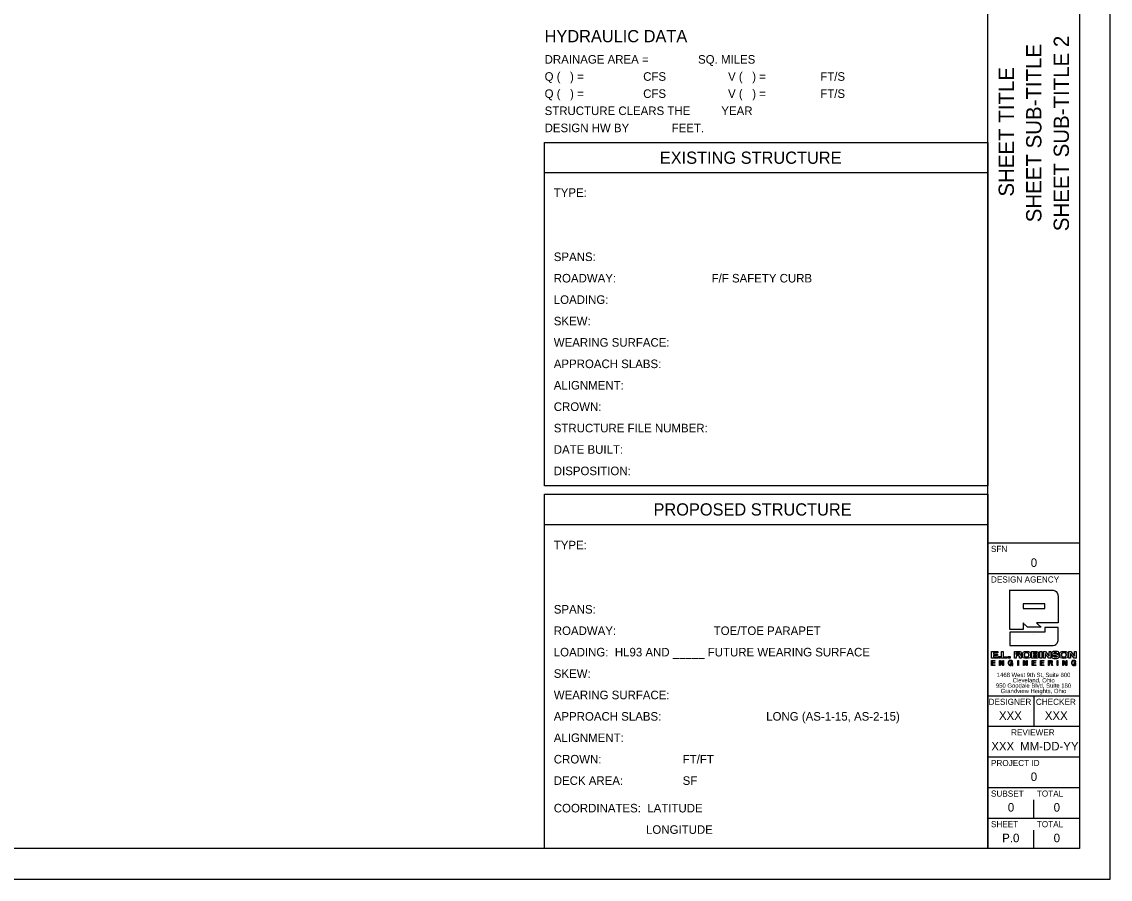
# Model space of a CAD drawing. Extents: x -1.6 to 34, y 0 to 22.
# Drawn here: x 16.2 to 34, y 0 to 14.02 of the extents above; entities that cross this region are included whole.
import ezdxf

# ---------------------------------------------------------------- set-up
doc = ezdxf.new("R2010")
doc.units = 0
for name, color, linetype in [('Default', 7, 'Continuous'), ('SH_Border', 7, 'Continuous'), ('SH_Cut_Line', 7, 'Continuous'), ('SH_Data', 7, 'Continuous')]:
    doc.layers.add(name, color=color, linetype=linetype)

msp = doc.modelspace()

# ---------------------------------------------------------------- linework, layer by layer
at = {"layer": 'SH_Border'}
for p, q in [((32, 0.5), (32, 21.5)), ((32, 5.5), (33.5, 5.5)), ((32, 5), (33.5, 5)), ((32, 3), (33.5, 3)), ((32.75, 3), (32.75, 2.5)), ((32, 2.5), (33.5, 2.5)), ((32, 2), (33.5, 2)), ((32, 1.5), (33.5, 1.5)), ((32, 1), (33.5, 1))]:
    msp.add_line(p, q, dxfattribs=at)
msp.add_lwpolyline([(1.5, 21.5), (33.5, 21.5), (33.5, 0.5), (1.5, 0.5)], close=True, dxfattribs=at)
at = {"layer": 'SH_Cut_Line'}
msp.add_lwpolyline([(0, 0), (34, 0), (34, 22), (0, 22)], close=True, dxfattribs=at)
at = {"layer": 'SH_Data'}
for p, q in [((32, 11.545), (24.75, 11.545)), ((32, 5.795), (24.75, 5.795)), ((32.929, 4.503), (32.574, 4.503)), ((32.574, 4.503), (32.574, 4.425)), ((32.929, 4.425), (32.929, 4.503)), ((32.574, 4.425), (32.929, 4.425)), ((32.75, 4), (32.75, 4)), ((32.463, 3.701), (32.463, 3.673)), ((32.743, 3.702), (32.743, 3.678)), ((32.743, 3.659), (32.743, 3.633)), ((33.001, 3.566), (33.001, 3.539)), ((33.001, 3.539), (33.023, 3.539)), ((32.75, 1), (32.75, 1.3)), ((32.75, 0.5), (32.75, 0.8)), ((32.375, 0.675), (32.375, 0.675))]:
    msp.add_line(p, q, dxfattribs=at)
for points in [[(24.75, 12.045), (32, 12.045), (32, 6.431), (24.75, 6.431)], [(24.75, 6.295), (32, 6.295), (32, 0.5), (24.75, 0.5)]]:
    msp.add_lwpolyline(points, close=True, dxfattribs=at)
for points in [[(32.059, 3.575), (32.114, 3.575), (32.114, 3.566), (32.07, 3.566), (32.07, 3.541), (32.111, 3.541), (32.111, 3.532), (32.07, 3.532), (32.07, 3.505), (32.114, 3.505), (32.114, 3.496), (32.059, 3.496), (32.059, 3.575)], [(32.06, 3.721), (32.161, 3.721), (32.161, 3.701), (32.089, 3.701), (32.089, 3.678), (32.158, 3.678), (32.158, 3.658), (32.089, 3.658), (32.089, 3.633), (32.162, 3.633), (32.162, 3.613), (32.06, 3.613), (32.06, 3.721)], [(32.175, 3.639), (32.205, 3.639), (32.205, 3.613), (32.175, 3.613), (32.175, 3.639)], [(32.191, 3.575), (32.203, 3.575), (32.244, 3.511), (32.244, 3.511), (32.244, 3.575), (32.254, 3.575), (32.254, 3.496), (32.243, 3.496), (32.202, 3.559), (32.201, 3.559), (32.201, 3.496), (32.191, 3.496), (32.191, 3.575)], [(32.22, 3.721), (32.249, 3.721), (32.249, 3.634), (32.316, 3.634), (32.316, 3.613), (32.22, 3.613), (32.22, 3.721)], [(32.331, 3.639), (32.361, 3.639), (32.361, 3.613), (32.331, 3.613), (32.331, 3.639)], [(32.487, 3.575), (32.498, 3.575), (32.498, 3.496), (32.487, 3.496), (32.487, 3.575)], [(32.581, 3.575), (32.592, 3.575), (32.633, 3.511), (32.633, 3.511), (32.633, 3.575), (32.643, 3.575), (32.643, 3.496), (32.632, 3.496), (32.591, 3.559), (32.591, 3.559), (32.591, 3.496), (32.581, 3.496), (32.581, 3.575)], [(32.726, 3.575), (32.781, 3.575), (32.781, 3.566), (32.737, 3.566), (32.737, 3.541), (32.778, 3.541), (32.778, 3.532), (32.737, 3.532), (32.737, 3.505), (32.781, 3.505), (32.781, 3.496), (32.726, 3.496), (32.726, 3.575)], [(32.851, 3.721), (32.881, 3.721), (32.881, 3.613), (32.851, 3.613), (32.851, 3.721)], [(32.859, 3.575), (32.913, 3.575), (32.913, 3.566), (32.869, 3.566), (32.869, 3.541), (32.91, 3.541), (32.91, 3.532), (32.869, 3.532), (32.869, 3.505), (32.913, 3.505), (32.913, 3.496), (32.859, 3.496), (32.859, 3.575)], [(32.999, 3.721), (33.027, 3.721), (33.027, 3.613), (32.995, 3.613), (32.936, 3.689), (32.936, 3.689), (32.936, 3.613), (32.907, 3.613), (32.907, 3.721), (32.941, 3.721), (32.999, 3.646), (32.999, 3.646), (32.999, 3.721)], [(33.133, 3.575), (33.143, 3.575), (33.143, 3.496), (33.133, 3.496), (33.133, 3.575)], [(33.226, 3.575), (33.237, 3.575), (33.279, 3.511), (33.279, 3.511), (33.279, 3.575), (33.289, 3.575), (33.289, 3.496), (33.277, 3.496), (33.236, 3.559), (33.236, 3.559), (33.236, 3.496), (33.226, 3.496), (33.226, 3.575)], [(33.413, 3.721), (33.442, 3.721), (33.442, 3.613), (33.41, 3.613), (33.35, 3.689), (33.35, 3.689), (33.35, 3.613), (33.321, 3.613), (33.321, 3.721), (33.356, 3.721), (33.413, 3.646), (33.413, 3.646), (33.413, 3.721)]]:
    msp.add_lwpolyline(points, dxfattribs=at)
for points, degree in [([(32.356, 4.083), (32.356, 4.086), (32.356, 4.724), (32.356, 4.727)], 2), ([(32.356, 4.727), (32.36, 4.727), (33.03, 4.727), (33.034, 4.727), (33.096, 4.727), (33.147, 4.677), (33.147, 4.614)], 3), ([(33.147, 4.614), (33.147, 4.612), (33.147, 4.194), (33.147, 4.192)], 2), ([(32.929, 4.115), (32.929, 4.115), (33.147, 4.115), (33.147, 4.115), (33.147, 4.115), (33.147, 3.933), (33.147, 3.933), (33.147, 3.87), (33.096, 3.82), (33.034, 3.82), (33.034, 3.82), (32.356, 3.82), (32.356, 3.82), (32.356, 3.82), (32.356, 4.037), (32.356, 4.037), (32.356, 4.037), (32.929, 4.037), (32.929, 4.037), (32.929, 4.037), (32.929, 4.115), (32.929, 4.115)], 3), ([(32.645, 4.121), (32.645, 4.121), (32.574, 4.191), (32.574, 4.192)], 2), ([(32.574, 4.192), (32.574, 4.191), (32.574, 4.083), (32.574, 4.083)], 2), ([(32.866, 4.121), (32.865, 4.121), (32.646, 4.121), (32.645, 4.121)], 2), ([(33.147, 4.192), (33.145, 4.192), (32.795, 4.192), (32.793, 4.192)], 2), ([(32.793, 4.192), (32.793, 4.191), (32.866, 4.121), (32.866, 4.121)], 2), ([(32.574, 4.083), (32.573, 4.083), (32.357, 4.083), (32.356, 4.083)], 2), ([(32.396, 3.506), (32.39, 3.498), (32.38, 3.494), (32.37, 3.494), (32.347, 3.494), (32.333, 3.514), (32.333, 3.534), (32.333, 3.557), (32.346, 3.577), (32.37, 3.577), (32.388, 3.577), (32.401, 3.569), (32.404, 3.551), (32.404, 3.551), (32.394, 3.551), (32.394, 3.551), (32.392, 3.562), (32.382, 3.568), (32.37, 3.568), (32.351, 3.568), (32.344, 3.551), (32.344, 3.534), (32.344, 3.518), (32.353, 3.503), (32.37, 3.503), (32.387, 3.503), (32.396, 3.515), (32.396, 3.529), (32.396, 3.529), (32.371, 3.529), (32.371, 3.529), (32.371, 3.529), (32.371, 3.538), (32.371, 3.538), (32.371, 3.538), (32.405, 3.538), (32.405, 3.538), (32.405, 3.538), (32.405, 3.496), (32.405, 3.496), (32.405, 3.496), (32.398, 3.496), (32.398, 3.496), (32.398, 3.496), (32.396, 3.506), (32.396, 3.506)], 3), ([(32.433, 3.613), (32.433, 3.613), (32.433, 3.721), (32.433, 3.721)], 2), ([(32.433, 3.721), (32.433, 3.721), (32.512, 3.721), (32.512, 3.721), (32.542, 3.721), (32.545, 3.703), (32.546, 3.692)], 3), ([(32.463, 3.613), (32.462, 3.613), (32.433, 3.613), (32.433, 3.613)], 2), ([(32.499, 3.653), (32.499, 3.653), (32.463, 3.653), (32.463, 3.653)], 2), ([(32.463, 3.673), (32.463, 3.673), (32.502, 3.673), (32.502, 3.673), (32.508, 3.673), (32.516, 3.677), (32.516, 3.687), (32.516, 3.698), (32.507, 3.701), (32.5, 3.701), (32.5, 3.701), (32.463, 3.701), (32.463, 3.701), (32.463, 3.701), (32.463, 3.673), (32.463, 3.673)], 3), ([(32.463, 3.673), (32.476, 3.673), (32.489, 3.673), (32.508, 3.673), (32.516, 3.677), (32.516, 3.698), (32.507, 3.701), (32.488, 3.701), (32.475, 3.701), (32.463, 3.701)], 3), ([(32.463, 3.653), (32.463, 3.652), (32.463, 3.613), (32.463, 3.613)], 2), ([(32.518, 3.613), (32.516, 3.618), (32.516, 3.622), (32.516, 3.634), (32.515, 3.649), (32.508, 3.65), (32.499, 3.653)], 3), ([(32.55, 3.613), (32.55, 3.613), (32.518, 3.613), (32.518, 3.613)], 2), ([(32.546, 3.692), (32.544, 3.679), (32.542, 3.67), (32.53, 3.666)], 2), ([(32.53, 3.666), (32.53, 3.666), (32.53, 3.665), (32.53, 3.665)], 2), ([(32.53, 3.665), (32.543, 3.663), (32.544, 3.647), (32.544, 3.636)], 2), ([(32.544, 3.636), (32.544, 3.631), (32.548, 3.619), (32.55, 3.613)], 2), ([(32.631, 3.61), (32.573, 3.61), (32.567, 3.645), (32.565, 3.667), (32.564, 3.69), (32.573, 3.724), (32.631, 3.724)], 3), ([(32.631, 3.63), (32.658, 3.63), (32.667, 3.65), (32.667, 3.667), (32.667, 3.684), (32.658, 3.704), (32.631, 3.704), (32.604, 3.704), (32.595, 3.684), (32.595, 3.667), (32.595, 3.65), (32.604, 3.63), (32.631, 3.63)], 3), ([(32.631, 3.704), (32.604, 3.704), (32.595, 3.684), (32.595, 3.667), (32.595, 3.65), (32.604, 3.63), (32.631, 3.63)], 3), ([(32.631, 3.724), (32.69, 3.724), (32.695, 3.689), (32.697, 3.667), (32.699, 3.644), (32.69, 3.61), (32.631, 3.61)], 3), ([(32.631, 3.63), (32.658, 3.63), (32.667, 3.65), (32.667, 3.667), (32.667, 3.684), (32.658, 3.704), (32.631, 3.704)], 3), ([(32.714, 3.613), (32.714, 3.613), (32.714, 3.721), (32.714, 3.721)], 2), ([(32.714, 3.721), (32.714, 3.721), (32.795, 3.721), (32.795, 3.721)], 2), ([(32.829, 3.645), (32.827, 3.632), (32.824, 3.613), (32.791, 3.613), (32.791, 3.613), (32.714, 3.613), (32.714, 3.613)], 3), ([(32.743, 3.678), (32.743, 3.678), (32.784, 3.678), (32.784, 3.678), (32.791, 3.678), (32.796, 3.682), (32.796, 3.69), (32.796, 3.697), (32.793, 3.702), (32.78, 3.702), (32.78, 3.702), (32.743, 3.702), (32.743, 3.702), (32.743, 3.702), (32.743, 3.678), (32.743, 3.678)], 3), ([(32.743, 3.678), (32.757, 3.678), (32.771, 3.678), (32.791, 3.681), (32.791, 3.683), (32.792, 3.697), (32.793, 3.702), (32.768, 3.702), (32.756, 3.702), (32.743, 3.702)], 3), ([(32.743, 3.633), (32.743, 3.633), (32.787, 3.633), (32.787, 3.633), (32.796, 3.633), (32.8, 3.639), (32.8, 3.646), (32.8, 3.655), (32.794, 3.659), (32.784, 3.659), (32.784, 3.659), (32.743, 3.659), (32.743, 3.659), (32.743, 3.659), (32.743, 3.633), (32.743, 3.633)], 3), ([(32.743, 3.633), (32.758, 3.633), (32.772, 3.633), (32.796, 3.633), (32.8, 3.639), (32.8, 3.655), (32.794, 3.659), (32.77, 3.659), (32.757, 3.659), (32.743, 3.659)], 3), ([(32.795, 3.721), (32.81, 3.718), (32.826, 3.714), (32.826, 3.694)], 2), ([(32.826, 3.694), (32.824, 3.686), (32.822, 3.675), (32.812, 3.672)], 2), ([(32.812, 3.672), (32.812, 3.672), (32.812, 3.672), (32.812, 3.672)], 2), ([(32.812, 3.672), (32.824, 3.67), (32.827, 3.656), (32.829, 3.645)], 2), ([(32.991, 3.575), (32.991, 3.575), (33.027, 3.575), (33.028, 3.575), (33.042, 3.575), (33.051, 3.567), (33.051, 3.554)], 3), ([(32.991, 3.496), (32.991, 3.497), (32.991, 3.574), (32.991, 3.575)], 2), ([(33.023, 3.539), (33.033, 3.539), (33.041, 3.541), (33.041, 3.552), (33.041, 3.56), (33.037, 3.566), (33.027, 3.566), (33.027, 3.566), (33.001, 3.566), (33.001, 3.566), (33.001, 3.566), (33.001, 3.539), (33.001, 3.539), (33.001, 3.539), (33.023, 3.539), (33.023, 3.539)], 3), ([(33.023, 3.539), (33.033, 3.539), (33.041, 3.541), (33.041, 3.56), (33.037, 3.566), (33.018, 3.566), (33.01, 3.566), (33.001, 3.566)], 3), ([(33.126, 3.69), (33.124, 3.704), (33.111, 3.706), (33.099, 3.706), (33.087, 3.706), (33.079, 3.7), (33.079, 3.693), (33.079, 3.687), (33.084, 3.684), (33.091, 3.683), (33.091, 3.683), (33.128, 3.677), (33.128, 3.677), (33.148, 3.673), (33.163, 3.666), (33.163, 3.646), (33.163, 3.626), (33.149, 3.61), (33.107, 3.61), (33.08, 3.61), (33.046, 3.613), (33.045, 3.647), (33.045, 3.647), (33.079, 3.647), (33.079, 3.647), (33.079, 3.632), (33.094, 3.629), (33.107, 3.629), (33.121, 3.629), (33.13, 3.634), (33.13, 3.643), (33.13, 3.651), (33.123, 3.654), (33.112, 3.655), (33.112, 3.655), (33.085, 3.66), (33.085, 3.66), (33.066, 3.662), (33.047, 3.668), (33.047, 3.69), (33.047, 3.715), (33.067, 3.724), (33.101, 3.724), (33.124, 3.724), (33.157, 3.721), (33.159, 3.69), (33.159, 3.69), (33.126, 3.69), (33.126, 3.69)], 3), ([(33.242, 3.61), (33.183, 3.61), (33.178, 3.645), (33.176, 3.667), (33.174, 3.69), (33.183, 3.724), (33.242, 3.724)], 3), ([(33.242, 3.63), (33.269, 3.63), (33.278, 3.65), (33.278, 3.667), (33.278, 3.684), (33.269, 3.704), (33.242, 3.704), (33.215, 3.704), (33.205, 3.684), (33.205, 3.667), (33.205, 3.65), (33.215, 3.63), (33.242, 3.63)], 3), ([(33.242, 3.704), (33.215, 3.704), (33.205, 3.684), (33.205, 3.667), (33.205, 3.65), (33.215, 3.63), (33.242, 3.63)], 3), ([(33.242, 3.724), (33.3, 3.724), (33.306, 3.689), (33.308, 3.667), (33.309, 3.644), (33.3, 3.61), (33.242, 3.61)], 3), ([(33.242, 3.63), (33.269, 3.63), (33.278, 3.65), (33.278, 3.667), (33.278, 3.684), (33.269, 3.704), (33.242, 3.704)], 3), ([(33.43, 3.506), (33.424, 3.498), (33.414, 3.494), (33.405, 3.494), (33.382, 3.494), (33.368, 3.514), (33.368, 3.534), (33.368, 3.557), (33.38, 3.577), (33.405, 3.577), (33.422, 3.577), (33.436, 3.569), (33.439, 3.551), (33.439, 3.551), (33.429, 3.551), (33.429, 3.551), (33.426, 3.562), (33.417, 3.568), (33.405, 3.568), (33.386, 3.568), (33.378, 3.551), (33.378, 3.534), (33.378, 3.518), (33.388, 3.503), (33.405, 3.503), (33.421, 3.503), (33.431, 3.515), (33.43, 3.529), (33.43, 3.529), (33.405, 3.529), (33.405, 3.529), (33.405, 3.529), (33.405, 3.538), (33.405, 3.538), (33.405, 3.538), (33.44, 3.538), (33.44, 3.538), (33.44, 3.538), (33.44, 3.496), (33.44, 3.496), (33.44, 3.496), (33.433, 3.496), (33.433, 3.496), (33.433, 3.496), (33.43, 3.506), (33.43, 3.506)], 3), ([(33.001, 3.496), (33.001, 3.496), (32.991, 3.496), (32.991, 3.496)], 2), ([(33.04, 3.516), (33.038, 3.523), (33.037, 3.53), (33.027, 3.53), (33.027, 3.53), (33.001, 3.53), (33.001, 3.53)], 3), ([(33.001, 3.53), (33.001, 3.53), (33.001, 3.496), (33.001, 3.496)], 2), ([(33.051, 3.554), (33.049, 3.545), (33.047, 3.537), (33.038, 3.534)], 2), ([(33.038, 3.534), (33.038, 3.534), (33.038, 3.534), (33.038, 3.534)], 2), ([(33.038, 3.534), (33.044, 3.529), (33.047, 3.525), (33.048, 3.518)], 2), ([(33.043, 3.496), (33.042, 3.5), (33.041, 3.508), (33.04, 3.516)], 2), ([(33.054, 3.496), (33.054, 3.496), (33.043, 3.496), (33.043, 3.496)], 2), ([(33.048, 3.518), (33.049, 3.51), (33.052, 3.502), (33.054, 3.496)], 2)]:
    msp.add_open_spline(points, degree=degree, dxfattribs=at)

# ---------------------------------------------------------------- texts
at = {"layer": 'Default'}
msp.add_text('0', height=0.14, dxfattribs=at).set_placement((32.7, 5.105))
at = {"layer": 'SH_Data'}
for s, height, p in [('HYDRAULIC DATA', 0.2, (24.75, 13.682)), ('DRAINAGE AREA =', 0.14, (24.75, 13.332)), ('SQ. MILES', 0.14, (27.259, 13.332)), ('Q (   ) =', 0.14, (24.75, 13.052)), ('      CFS', 0.14, (26.05, 13.052)), ('V (   ) =', 0.14, (27.75, 13.052)), ('    FT/S', 0.14, (29.05, 13.052)), ('Q (   ) =', 0.14, (24.75, 12.772)), ('      CFS', 0.14, (26.05, 12.772)), ('V (   ) =', 0.14, (27.75, 12.772)), ('    FT/S', 0.14, (29.05, 12.772)), ('STRUCTURE CLEARS THE', 0.14, (24.75, 12.492)), ('YEAR', 0.14, (27.64, 12.492)), ('DESIGN HW BY', 0.14, (24.75, 12.212)), ('FEET.', 0.14, (26.827, 12.212)), ('EXISTING STRUCTURE', 0.2, (26.634, 11.695)), ('TYPE:', 0.14, (24.9, 11.155)), ('SPANS:', 0.14, (24.9, 10.105)), ('ROADWAY:', 0.14, (24.9, 9.755)), ('F/F SAFETY CURB', 0.14, (27.481, 9.755)), ('LOADING:', 0.14, (24.9, 9.405)), ('SKEW:', 0.14, (24.9, 9.055)), ('WEARING SURFACE:', 0.14, (24.9, 8.705)), ('APPROACH SLABS:', 0.14, (24.9, 8.355)), ('ALIGNMENT:', 0.14, (24.9, 8.005)), ('CROWN:', 0.14, (24.9, 7.655)), ('STRUCTURE FILE NUMBER:', 0.14, (24.9, 7.305)), ('DATE BUILT:', 0.14, (24.9, 6.955)), ('DISPOSITION:', 0.14, (24.9, 6.605)), ('PROPOSED STRUCTURE', 0.2, (26.531, 5.945)), ('TYPE:', 0.14, (24.9, 5.392)), ('SFN', 0.1, (32.05, 5.35)), ('DESIGN AGENCY', 0.1, (32.05, 4.85)), ('SPANS:', 0.14, (24.9, 4.342)), ('ROADWAY:', 0.14, (24.9, 3.992)), ('TOE/TOE PARAPET', 0.14, (27.515, 3.992)), ('LOADING:  HL93 AND _____ FUTURE WEARING SURFACE', 0.14, (24.9, 3.642)), ('SKEW:', 0.14, (24.9, 3.292)), ('1468 West 9th St, Suite 800', 0.07, (32.145, 3.305)), ('Cleveland, Ohio', 0.07, (32.404, 3.217)), ('WEARING SURFACE:', 0.14, (24.9, 2.942)), ('950 Goodale Blvd, Suite 180', 0.07, (32.13, 3.13)), ('Grandview Heights, Ohio', 0.07, (32.208, 3.042)), ('DESIGNER', 0.1, (32.011, 2.85)), ('CHECKER', 0.1, (32.784, 2.85)), ('APPROACH SLABS:', 0.14, (24.9, 2.592)), ('LONG (AS-1-15, AS-2-15)', 0.14, (28.374, 2.592)), ('XXX', 0.14, (32.18, 2.605)), ('XXX', 0.14, (32.93, 2.605)), ('ALIGNMENT:', 0.14, (24.9, 2.242)), ('REVIEWER', 0.1, (32.378, 2.35)), ('XXX', 0.14, (32.055, 2.105)), ('MM-DD-YY', 0.14, (32.526, 2.105)), ('CROWN:', 0.14, (24.9, 1.892)), ('FT/FT', 0.14, (27.008, 1.892)), ('PROJECT ID', 0.1, (32.05, 1.85)), ('DECK AREA:', 0.14, (24.9, 1.542)), ('SF', 0.14, (27.008, 1.542)), ('0', 0.14, (32.7, 1.605)), ('SUBSET', 0.1, (32.05, 1.35)), ('TOTAL', 0.1, (32.8, 1.35)), ('0', 0.14, (32.325, 1.105)), ('0', 0.14, (33.075, 1.105)), ('COORDINATES:  LATITUDE', 0.14, (24.9, 1.092)), ('SHEET', 0.1, (32.05, 0.85)), ('TOTAL', 0.1, (32.8, 0.85)), ('                             LONGITUDE', 0.14, (24.9, 0.742)), ('P.0', 0.14, (32.233, 0.605)), ('0', 0.14, (33.075, 0.605))]:
    msp.add_text(s, height=height, dxfattribs=at).set_placement(p)
for s, p in [('SHEET SUB-TITLE 2', (33.325, 10.593)), ('SHEET SUB-TITLE', (32.875, 10.739)), ('SHEET TITLE', (32.425, 11.159))]:
    msp.add_text(s, height=0.25, rotation=90, dxfattribs=at).set_placement(p)

doc.saveas('drawing.dxf')
